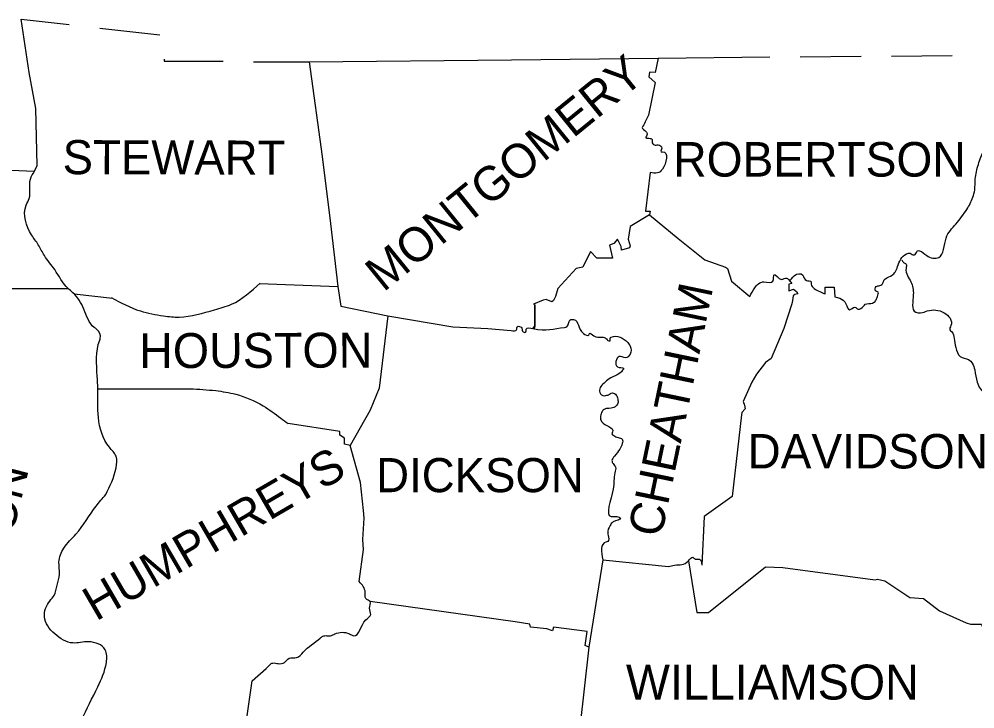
# Model space of a CAD drawing. Extents: x 1577619 to 1828281, y 483481 to 598136.
# Drawn here: x 1700423 to 1703569, y 531751 to 534020 of the extents above; entities that cross this region are included whole.
import ezdxf

# ---------------------------------------------------------------- set-up
doc = ezdxf.new("R2010")
doc.units = 0
doc.layers.add('DESIGN - SHEET - Corner Text', color=7, linetype='Continuous')
doc.layers.add('DESIGN - SHEET - Linework', color=7, linetype='Continuous')

msp = doc.modelspace()

# ---------------------------------------------------------------- linework, layer by layer
at = {"layer": 'DESIGN - SHEET - Linework'}
for p, q in [((1700688.2, 533989.6), (1700886.2, 533967.6)), ((1702994.2, 533895.6), (1703194.2, 533897.6)), ((1703294.2, 533897.6), (1703494.2, 533899.6))]:
    msp.add_line(p, q, dxfattribs=at)
for points in [[(1700290.2, 533527.6), (1700474.2, 533519.6), (1700482.2, 533537.6), (1700478.2, 533725.6), (1700456.2, 533843.6), (1700430.2, 534019.6), (1700588.2, 534001.6)], [(1702044.2, 533885.6), (1702526.2, 533891.6), (1702894.2, 533895.6)], [(1700900.2, 533887.6), (1700900.2, 533881.6), (1701094.2, 533881.6)], [(1701194.2, 533879.6), (1701378.2, 533879.6), (1702044.2, 533885.6)], [(1701378.2, 533879.6), (1701420.2, 533567.6), (1701448.2, 533347.6), (1701472.2, 533139.6), (1701482.2, 533075.6), (1701636.2, 533043.6), (1701850.2, 533007.6), (1701966.2, 533001.6), (1702042.2, 532995.6)], [(1702526.2, 533891.6), (1702516.2, 533843.6), (1702498.2, 533845.6), (1702496.2, 533829.6), (1702516.2, 533811.6), (1702494.2, 533703.6)], [(1702500.2, 533515.6), (1702484.2, 533387.6), (1702500.2, 533387.6), (1702498.2, 533375.6), (1702434.2, 533337.6), (1702428.2, 533295.6), (1702434.2, 533273.6), (1702432.2, 533267.6), (1702406.2, 533259.6), (1702404.2, 533271.6), (1702392.2, 533295.6), (1702380.2, 533281.6), (1702366.2, 533275.6), (1702376.2, 533233.6), (1702324.2, 533233.6), (1702304.2, 533255.6), (1702278.2, 533203.6), (1702256.2, 533199.6), (1702196.2, 533133.6), (1702188.2, 533107.6), (1702182.2, 533093.6), (1702176.2, 533089.6), (1702158.2, 533097.6), (1702148.2, 533095.6), (1702116.2, 533081.6), (1702120.2, 533079.6), (1702120.2, 533009.6), (1702118.2, 533001.6)], [(1702498.2, 533375.6), (1702592.2, 533297.6), (1702680.2, 533227.6), (1702748.2, 533203.6), (1702754.2, 533199.6), (1702768.2, 533157.6), (1702828.2, 533107.6)], [(1701214.2, 533149.6), (1701472.2, 533139.6)], [(1702956.2, 533161.6), (1702966.2, 533149.6), (1702956.2, 533147.6), (1702956.2, 533125.6), (1702972.2, 533131.6), (1702982.2, 533123.6), (1702986.2, 533115.6), (1702976.2, 533113.6), (1702970.2, 533109.6), (1702968.2, 533093.6), (1702966.2, 533083.6), (1702940.2, 533001.6), (1702898.2, 532903.6), (1702880.2, 532889.6), (1702850.2, 532851.6), (1702834.2, 532825.6), (1702806.2, 532761.6), (1702810.2, 532749.6), (1702812.2, 532737.6), (1702802.2, 532725.6), (1702800.2, 532717.6), (1702770.2, 532449.6), (1702678.2, 532383.6), (1702670.2, 532223.6)], [(1700352.2, 533133.6), (1700584.2, 533133.6)], [(1700604.2, 533115.6), (1700730.2, 533101.6)], [(1703076.2, 533115.6), (1703076.2, 533137.6), (1703106.2, 533137.6), (1703108.2, 533105.6)], [(1702114.2, 533001.6), (1702120.2, 533009.6), (1702120.2, 533079.6)], [(1701636.2, 533043.6), (1701608.2, 532805.6), (1701578.2, 532733.6), (1701512.2, 532617.6)], [(1700682.2, 532803.6), (1700986.2, 532803.6)], [(1701542.2, 532169.6), (1701556.2, 532275.6), (1701554.2, 532307.6), (1701558.2, 532377.6), (1701556.2, 532403.6), (1701546.2, 532495.6), (1701512.2, 532617.6), (1701494.2, 532621.6), (1701494.2, 532641.6), (1701478.2, 532651.6), (1701478.2, 532663.6), (1701308.2, 532689.6)], [(1702344.2, 532241.6), (1702298.2, 531953.6), (1702268.2, 531689.6), (1702224.2, 531359.6), (1702174.2, 531339.6)], [(1702344.2, 532241.6), (1702560.2, 532219.6)], [(1702626.2, 532237.6), (1702654.2, 532067.6), (1702692.2, 532067.6), (1702880.2, 532217.6), (1702936.2, 532215.6), (1703240.2, 532175.6), (1703248.2, 532177.6), (1703272.2, 532171.6), (1703354.2, 532117.6), (1703400.2, 532113.6), (1703452.2, 532073.6), (1703540.2, 532033.6), (1703554.2, 532029.6), (1703590.2, 532029.6), (1703594.2, 532019.6), (1703610.2, 532021.6), (1703616.2, 532017.6), (1703626.2, 532025.6)], [(1702298.2, 531953.6), (1702286.2, 531959.6), (1702292.2, 532005.6), (1702182.2, 532019.6), (1702178.2, 532007.6), (1702160.2, 532013.6), (1702106.2, 532019.6), (1702104.2, 532029.6), (1702056.2, 532037.6), (1701578.2, 532103.6)], [(1701168.2, 531689.6), (1701190.2, 531843.6), (1701236.2, 531883.6), (1701252.2, 531899.6)]]:
    msp.add_lwpolyline(points, dxfattribs=at)
for points in [[(1703108.2, 533105.6), (1703124.2, 533101.6), (1703144.2, 533083.6), (1703156.2, 533063.6), (1703174.2, 533071.6), (1703184.2, 533065.6), (1703202.2, 533075.6), (1703208.2, 533081.6), (1703232.2, 533085.6), (1703242.2, 533093.6), (1703248.2, 533107.6), (1703250.2, 533121.6), (1703242.2, 533125.6), (1703244.2, 533139.6), (1703256.2, 533143.6), (1703266.2, 533151.6), (1703270.2, 533161.6), (1703274.2, 533165.6), (1703296.2, 533177.6), (1703306.2, 533187.6), (1703314.2, 533205.6), (1703344.2, 533247.6), (1703356.2, 533249.6), (1703362.2, 533245.6), (1703372.2, 533245.6), (1703380.2, 533257.6), (1703386.2, 533257.6), (1703410.2, 533241.6), (1703450.2, 533235.6), (1703474.2, 533299.6), (1703506.2, 533345.6), (1703542.2, 533393.6), (1703562.2, 533433.6), (1703568.2, 533457.6), (1703570.2, 533493.6), (1703580.2, 533541.6), (1703588.2, 533565.6), (1703602.2, 533595.6), (1703630.2, 533643.6), (1703660.2, 533693.6), (1703694.2, 533765.6), (1703744.2, 533825.6), (1703752.2, 533843.6)], [(1702494.2, 533703.6), (1702476.2, 533667.6), (1702474.2, 533663.6), (1702486.2, 533649.6), (1702490.2, 533641.6), (1702486.2, 533629.6), (1702496.2, 533627.6), (1702506.2, 533623.6), (1702506.2, 533615.6), (1702514.2, 533605.6), (1702526.2, 533605.6), (1702538.2, 533595.6), (1702536.2, 533583.6), (1702540.2, 533583.6), (1702540.2, 533525.6), (1702524.2, 533513.6), (1702500.2, 533515.6)], [(1700708.2, 532455.6), (1700742.2, 532543.6), (1700742.2, 532581.6), (1700720.2, 532611.6), (1700684.2, 532709.6), (1700682.2, 532803.6), (1700680.2, 532845.6), (1700688.2, 532963.6), (1700690.2, 532969.6), (1700678.2, 532999.6), (1700670.2, 533005.6), (1700636.2, 533065.6), (1700600.2, 533119.6), (1700584.2, 533133.6), (1700540.2, 533195.6), (1700506.2, 533241.6), (1700486.2, 533277.6), (1700464.2, 533309.6), (1700446.2, 533407.6), (1700456.2, 533429.6), (1700460.2, 533493.6), (1700474.2, 533519.6)], [(1703328.2, 533227.6), (1703334.2, 533219.6), (1703342.2, 533213.6), (1703342.2, 533199.6), (1703358.2, 533155.6), (1703366.2, 533113.6), (1703374.2, 533055.6), (1703390.2, 533053.6), (1703412.2, 533059.6), (1703468.2, 533053.6), (1703490.2, 533011.6), (1703486.2, 532997.6), (1703492.2, 532991.6), (1703500.2, 532969.6), (1703506.2, 532939.6), (1703520.2, 532909.6), (1703548.2, 532899.6), (1703560.2, 532887.6), (1703568.2, 532865.6), (1703576.2, 532825.6), (1703602.2, 532787.6), (1703618.2, 532779.6), (1703648.2, 532779.6), (1703662.2, 532781.6), (1703678.2, 532781.6), (1703726.2, 532827.6), (1703748.2, 532883.6), (1703752.2, 532929.6), (1703754.2, 532953.6), (1703760.2, 532965.6), (1703770.2, 532971.6), (1703782.2, 532971.6), (1703794.2, 532947.6), (1703796.2, 532919.6), (1703802.2, 532899.6), (1703826.2, 532881.6), (1703852.2, 532883.6), (1703860.2, 532905.6), (1703872.2, 532927.6), (1703916.2, 532969.6), (1703944.2, 532989.6), (1703980.2, 533015.6), (1704014.2, 533029.6), (1704048.2, 533015.6), (1704064.2, 532997.6), (1704072.2, 532971.6), (1704088.2, 532959.6), (1704108.2, 532951.6), (1704126.2, 532951.6), (1704136.2, 532963.6), (1704146.2, 533029.6), (1704158.2, 533051.6), (1704170.2, 533063.6), (1704188.2, 533071.6), (1704216.2, 533063.6), (1704232.2, 533011.6), (1704224.2, 532997.6), (1704200.2, 532967.6), (1704206.2, 532945.6), (1704224.2, 532945.6), (1704278.2, 532963.6), (1704302.2, 532959.6), (1704324.2, 532957.6), (1704344.2, 532969.6), (1704344.2, 533019.6), (1704348.2, 533037.6), (1704372.2, 533047.6), (1704394.2, 533041.6), (1704408.2, 533031.6), (1704412.2, 533013.6), (1704398.2, 532963.6), (1704394.2, 532941.6), (1704410.2, 532929.6), (1704430.2, 532927.6), (1704458.2, 532945.6), (1704464.2, 532963.6), (1704460.2, 532989.6), (1704460.2, 533007.6), (1704472.2, 533031.6), (1704492.2, 533031.6), (1704492.2, 533023.6), (1704530.2, 533021.6), (1704534.2, 533031.6), (1704550.2, 533029.6), (1704550.2, 533009.6), (1704570.2, 532981.6), (1704586.2, 532979.6), (1704604.2, 532995.6)], [(1702828.2, 533107.6), (1702844.2, 533135.6), (1702874.2, 533155.6), (1702904.2, 533157.6), (1702908.2, 533179.6), (1702932.2, 533163.6), (1702950.2, 533167.6), (1702958.2, 533161.6), (1702974.2, 533175.6), (1703002.2, 533177.6), (1703014.2, 533159.6), (1703030.2, 533155.6), (1703030.2, 533147.6), (1703040.2, 533133.6), (1703076.2, 533115.6)], [(1700726.2, 533103.6), (1700822.2, 533059.6), (1700898.2, 533043.6), (1700950.2, 533039.6), (1701066.2, 533063.6), (1701122.2, 533081.6), (1701216.2, 533151.6)], [(1702042.2, 532995.6), (1702060.2, 532997.6), (1702062.2, 533007.6), (1702078.2, 533003.6), (1702080.2, 532993.6), (1702090.2, 532989.6), (1702092.2, 532999.6), (1702114.2, 533001.6), (1702218.2, 533005.6), (1702226.2, 533007.6), (1702236.2, 533029.6), (1702248.2, 533031.6), (1702280.2, 532985.6), (1702298.2, 532981.6), (1702300.2, 532985.6), (1702314.2, 532977.6), (1702342.2, 532973.6), (1702354.2, 532969.6), (1702364.2, 532961.6), (1702368.2, 532961.6), (1702368.2, 532969.6), (1702372.2, 532973.6), (1702426.2, 532955.6), (1702434.2, 532943.6), (1702434.2, 532917.6), (1702418.2, 532905.6), (1702398.2, 532909.6), (1702392.2, 532875.6), (1702412.2, 532871.6), (1702400.2, 532855.6), (1702370.2, 532839.6), (1702352.2, 532825.6), (1702338.2, 532811.6), (1702334.2, 532803.6), (1702336.2, 532787.6), (1702344.2, 532781.6), (1702354.2, 532781.6), (1702366.2, 532785.6), (1702372.2, 532789.6), (1702386.2, 532785.6), (1702392.2, 532773.6), (1702394.2, 532759.6), (1702388.2, 532747.6), (1702380.2, 532741.6), (1702348.2, 532735.6), (1702340.2, 532725.6), (1702336.2, 532709.6), (1702340.2, 532695.6), (1702376.2, 532661.6), (1702374.2, 532655.6), (1702380.2, 532649.6), (1702394.2, 532643.6), (1702408.2, 532637.6), (1702408.2, 532623.6), (1702400.2, 532605.6), (1702382.2, 532581.6), (1702374.2, 532567.6), (1702378.2, 532557.6), (1702386.2, 532545.6), (1702384.2, 532527.6), (1702378.2, 532473.6), (1702372.2, 532383.6), (1702390.2, 532383.6), (1702402.2, 532377.6), (1702378.2, 532365.6), (1702368.2, 532353.6), (1702360.2, 532329.6), (1702362.2, 532321.6), (1702360.2, 532301.6), (1702354.2, 532299.6), (1702344.2, 532241.6)], [(1700986.2, 532803.6), (1701070.2, 532797.6), (1701136.2, 532785.6), (1701226.2, 532747.6), (1701284.2, 532707.6), (1701308.2, 532689.6)], [(1699970.2, 530557.6), (1699978.2, 530559.6), (1699990.2, 530561.6), (1699998.2, 530559.6), (1700006.2, 530549.6), (1700014.2, 530547.6), (1700032.2, 530533.6), (1700046.2, 530529.6), (1700052.2, 530513.6), (1700062.2, 530499.6), (1700062.2, 530493.6), (1700066.2, 530485.6), (1700088.2, 530461.6), (1700094.2, 530457.6), (1700096.2, 530453.6), (1700112.2, 530461.6), (1700152.2, 530473.6), (1700184.2, 530459.6), (1700214.2, 530453.6), (1700232.2, 530453.6), (1700298.2, 530495.6), (1700308.2, 530507.6), (1700322.2, 530515.6), (1700338.2, 530525.6), (1700352.2, 530531.6), (1700380.2, 530531.6), (1700390.2, 530525.6), (1700432.2, 530493.6), (1700446.2, 530481.6), (1700466.2, 530469.6), (1700492.2, 530467.6), (1700534.2, 530475.6), (1700560.2, 530485.6), (1700574.2, 530503.6), (1700574.2, 530521.6), (1700568.2, 530531.6), (1700558.2, 530537.6), (1700534.2, 530543.6), (1700524.2, 530547.6), (1700506.2, 530549.6), (1700478.2, 530559.6), (1700450.2, 530575.6), (1700436.2, 530587.6), (1700428.2, 530615.6), (1700428.2, 530649.6), (1700430.2, 530669.6), (1700440.2, 530681.6), (1700454.2, 530689.6), (1700474.2, 530697.6), (1700502.2, 530709.6), (1700530.2, 530715.6), (1700542.2, 530723.6), (1700556.2, 530745.6), (1700570.2, 530767.6), (1700582.2, 530789.6), (1700578.2, 530815.6), (1700556.2, 530865.6), (1700542.2, 530887.6), (1700520.2, 530931.6), (1700508.2, 530951.6), (1700480.2, 531025.6), (1700462.2, 531063.6), (1700458.2, 531117.6), (1700464.2, 531147.6), (1700478.2, 531167.6), (1700482.2, 531185.6), (1700484.2, 531265.6), (1700472.2, 531293.6), (1700466.2, 531295.6), (1700458.2, 531331.6), (1700460.2, 531361.6), (1700476.2, 531407.6), (1700532.2, 531457.6), (1700554.2, 531465.6), (1700584.2, 531561.6), (1700600.2, 531641.6), (1700628.2, 531713.6), (1700682.2, 531823.6), (1700710.2, 531903.6), (1700706.2, 531945.6), (1700652.2, 531971.6), (1700600.2, 531967.6), (1700540.2, 531997.6), (1700506.2, 532053.6), (1700524.2, 532105.6), (1700538.2, 532123.6), (1700548.2, 532157.6), (1700556.2, 532193.6), (1700554.2, 532233.6), (1700570.2, 532279.6), (1700610.2, 532325.6), (1700676.2, 532417.6), (1700708.2, 532455.6)], [(1702560.2, 532219.6), (1702580.2, 532223.6), (1702626.2, 532237.6), (1702640.2, 532249.6), (1702648.2, 532243.6), (1702662.2, 532243.6), (1702670.2, 532223.6)], [(1701252.2, 531899.6), (1701258.2, 531901.6), (1701276.2, 531899.6), (1701296.2, 531903.6), (1701312.2, 531917.6), (1701336.2, 531919.6), (1701358.2, 531937.6), (1701414.2, 531983.6), (1701422.2, 531989.6), (1701436.2, 531991.6), (1701448.2, 531991.6), (1701462.2, 531997.6), (1701510.2, 531997.6), (1701524.2, 531991.6), (1701564.2, 532043.6), (1701580.2, 532061.6), (1701576.2, 532081.6), (1701578.2, 532103.6), (1701564.2, 532113.6), (1701562.2, 532133.6), (1701542.2, 532169.6)]]:
    msp.add_spline(points, degree=3, dxfattribs=at)

# ---------------------------------------------------------------- texts
at = {"layer": 'DESIGN - SHEET - Corner Text'}
for s, height, rotation, p in [('MONTGOMERY', 112.75, 39.0648, (1701622.2, 533119.6)), ('STEWART', 112.16, 359.8571, (1700566.2, 533509.6)), ('CHEATHAM', 112.3, 78.252, (1702536.2, 532311.6)), ('HOUSTON', 114.82, 0.1436, (1700818.2, 532871.6)), ('HUMPHREYS', 112.37, 30.1445, (1700676.2, 532037.6)), ('BENTON', 112.04, 75.7603, (1700302.2, 531933.6))]:
    msp.add_text(s, height=height, rotation=rotation, dxfattribs=at).set_placement(p)
for s, height, p in [('ROBERTSON', 113.62, (1702576.2, 533501.6)), ('DAVIDSON', 113.36, (1702820.2, 532541.6)), ('DICKSON', 112.16, (1701598.2, 532463.6)), ('WILLIAMSON', 114.82, (1702420.2, 531781.6))]:
    msp.add_text(s, height=height, dxfattribs=at).set_placement(p)

doc.saveas('drawing.dxf')
